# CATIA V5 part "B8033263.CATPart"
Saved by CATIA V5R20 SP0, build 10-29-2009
Part number: B8033263
Revision: 5
Definition: design
Nomenclature: B8033263
Source: made
Description: NOT SPECIFIED
Bounding box of the stored display mesh (mm): x -25 to 25, y -25 to 25, z 0 to 63
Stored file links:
  C:\Users\Utente\Desktop\3D files B803\B8033263.CATPart
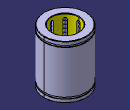
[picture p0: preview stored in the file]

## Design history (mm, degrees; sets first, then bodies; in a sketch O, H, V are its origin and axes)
Body1 "MANIFOLD_SOLID_BREP #38" (main body)
  Solid1: solid without history
Body2 "MANIFOLD_SOLID_BREP #76"
  Solid2: solid without history
Body3 "MANIFOLD_SOLID_BREP #114"
  Solid3: solid without history
Body4 "MANIFOLD_SOLID_BREP #152"
  Solid4: solid without history
Body5 "MANIFOLD_SOLID_BREP #190"
  Solid5: solid without history
Body6 "MANIFOLD_SOLID_BREP #228"
  Solid6: solid without history
Body7 "MANIFOLD_SOLID_BREP #266"
  Solid7: solid without history
Body8 "MANIFOLD_SOLID_BREP #304"
  Solid8: solid without history
Body9 "MANIFOLD_SOLID_BREP #2444"
  Solid9: solid without history
Body10 "MANIFOLD_SOLID_BREP #2482"
  Solid10: solid without history
Body11 "MANIFOLD_SOLID_BREP #2520"
  Solid11: solid without history
Body12 "MANIFOLD_SOLID_BREP #2558"
  Solid12: solid without history
Body13 "MANIFOLD_SOLID_BREP #2596"
  Solid13: solid without history
Body14 "MANIFOLD_SOLID_BREP #2634"
  Solid14: solid without history
Body15 "MANIFOLD_SOLID_BREP #2672"
  Solid15: solid without history
Body16 "MANIFOLD_SOLID_BREP #2710"
  Solid16: solid without history
Body17 "MANIFOLD_SOLID_BREP #2748"
  Solid17: solid without history
Body18 "MANIFOLD_SOLID_BREP #2786"
  Solid18: solid without history
Body19 "MANIFOLD_SOLID_BREP #2824"
  Solid19: solid without history
Body20 "MANIFOLD_SOLID_BREP #2862"
  Solid20: solid without history
Body21 "MANIFOLD_SOLID_BREP #2900"
  Solid21: solid without history
Body22 "MANIFOLD_SOLID_BREP #2938"
  Solid22: solid without history
Body23 "MANIFOLD_SOLID_BREP #2976"
  Solid23: solid without history
Body24 "MANIFOLD_SOLID_BREP #3014"
  Solid24: solid without history
Body25 "MANIFOLD_SOLID_BREP #3052"
  Solid25: solid without history
Body26 "MANIFOLD_SOLID_BREP #3090"
  Solid26: solid without history
Body27 "MANIFOLD_SOLID_BREP #3128"
  Solid27: solid without history
Body28 "MANIFOLD_SOLID_BREP #3166"
  Solid28: solid without history
Body29 "MANIFOLD_SOLID_BREP #3204"
  Solid29: solid without history
Body30 "MANIFOLD_SOLID_BREP #3242"
  Solid30: solid without history
Body31 "MANIFOLD_SOLID_BREP #3280"
  Solid31: solid without history
Body32 "MANIFOLD_SOLID_BREP #3318"
  Solid32: solid without history
Body33 "MANIFOLD_SOLID_BREP #3356"
  Solid33: solid without history
Body34 "MANIFOLD_SOLID_BREP #3394"
  Solid34: solid without history
Body35 "MANIFOLD_SOLID_BREP #3432"
  Solid35: solid without history
Body36 "MANIFOLD_SOLID_BREP #3470"
  Solid36: solid without history
Body37 "MANIFOLD_SOLID_BREP #3508"
  Solid37: solid without history
Body38 "MANIFOLD_SOLID_BREP #3546"
  Solid38: solid without history
Body39 "MANIFOLD_SOLID_BREP #3584"
  Solid39: solid without history
Body40 "MANIFOLD_SOLID_BREP #3622"
  Solid40: solid without history
Body41 "MANIFOLD_SOLID_BREP #3660"
  Solid41: solid without history
Body42 "MANIFOLD_SOLID_BREP #3698"
  Solid42: solid without history
Body43 "MANIFOLD_SOLID_BREP #3736"
  Solid43: solid without history
Body44 "MANIFOLD_SOLID_BREP #3774"
  Solid44: solid without history
Body45 "MANIFOLD_SOLID_BREP #3812"
  Solid45: solid without history
Body46 "MANIFOLD_SOLID_BREP #3850"
  Solid46: solid without history
Body47 "MANIFOLD_SOLID_BREP #3888"
  Solid47: solid without history
Body48 "MANIFOLD_SOLID_BREP #3926"
  Solid48: solid without history
Body49 "MANIFOLD_SOLID_BREP #3964"
  Solid49: solid without history
Body50 "MANIFOLD_SOLID_BREP #4002"
  Solid50: solid without history
Body51 "MANIFOLD_SOLID_BREP #4040"
  Solid51: solid without history
Body52 "MANIFOLD_SOLID_BREP #4078"
  Solid52: solid without history
Body53 "MANIFOLD_SOLID_BREP #4116"
  Solid53: solid without history
Body54 "MANIFOLD_SOLID_BREP #4154"
  Solid54: solid without history
Body55 "MANIFOLD_SOLID_BREP #4192"
  Solid55: solid without history
Body56 "MANIFOLD_SOLID_BREP #4230"
  Solid56: solid without history
Body57 "MANIFOLD_SOLID_BREP #4268"
  Solid57: solid without history
Body58 "MANIFOLD_SOLID_BREP #4306"
  Solid58: solid without history
Body59 "MANIFOLD_SOLID_BREP #4344"
  Solid59: solid without history
Body60 "MANIFOLD_SOLID_BREP #4382"
  Solid60: solid without history
Body61 "MANIFOLD_SOLID_BREP #4420"
  Solid61: solid without history
Body62 "MANIFOLD_SOLID_BREP #4458"
  Solid62: solid without history
Body63 "MANIFOLD_SOLID_BREP #4496"
  Solid63: solid without history
Body64 "MANIFOLD_SOLID_BREP #4534"
  Solid64: solid without history
Body65 "MANIFOLD_SOLID_BREP #4572"
  Solid65: solid without history
Body66 "MANIFOLD_SOLID_BREP #4610"
  Solid66: solid without history
Body67 "MANIFOLD_SOLID_BREP #4648"
  Solid67: solid without history
Body68 "MANIFOLD_SOLID_BREP #4686"
  Solid68: solid without history
Body69 "MANIFOLD_SOLID_BREP #4724"
  Solid69: solid without history
Body70 "MANIFOLD_SOLID_BREP #4762"
  Solid70: solid without history
Body71 "MANIFOLD_SOLID_BREP #4800"
  Solid71: solid without history
Body72 "MANIFOLD_SOLID_BREP #4838"
  Solid72: solid without history
Body73 "MANIFOLD_SOLID_BREP #4876"
  Solid73: solid without history
Body74 "MANIFOLD_SOLID_BREP #4914"
  Solid74: solid without history
Body75 "MANIFOLD_SOLID_BREP #4952"
  Solid75: solid without history
Body76 "MANIFOLD_SOLID_BREP #4990"
  Solid76: solid without history
Body77 "MANIFOLD_SOLID_BREP #5028"
  Solid77: solid without history
Body78 "MANIFOLD_SOLID_BREP #5066"
  Solid78: solid without history
Body79 "MANIFOLD_SOLID_BREP #5104"
  Solid79: solid without history
Body80 "MANIFOLD_SOLID_BREP #5142"
  Solid80: solid without history
Body81 "MANIFOLD_SOLID_BREP #5180"
  Solid81: solid without history
Body82 "MANIFOLD_SOLID_BREP #5218"
  Solid82: solid without history
Body83 "MANIFOLD_SOLID_BREP #5256"
  Solid83: solid without history
Body84 "MANIFOLD_SOLID_BREP #5294"
  Solid84: solid without history
Body85 "MANIFOLD_SOLID_BREP #5332"
  Solid85: solid without history
Body86 "MANIFOLD_SOLID_BREP #5370"
  Solid86: solid without history
Body87 "MANIFOLD_SOLID_BREP #5408"
  Solid87: solid without history
Body88 "MANIFOLD_SOLID_BREP #5446"
  Solid88: solid without history
Body89 "MANIFOLD_SOLID_BREP #5484"
  Solid89: solid without history
Body90 "MANIFOLD_SOLID_BREP #5522"
  Solid90: solid without history
Body91 "MANIFOLD_SOLID_BREP #5560"
  Solid91: solid without history
Body92 "MANIFOLD_SOLID_BREP #5598"
  Solid92: solid without history
Body93 "MANIFOLD_SOLID_BREP #5636"
  Solid93: solid without history
Body94 "MANIFOLD_SOLID_BREP #5674"
  Solid94: solid without history
Body95 "MANIFOLD_SOLID_BREP #5712"
  Solid95: solid without history
Body96 "MANIFOLD_SOLID_BREP #5750"
  Solid96: solid without history
Body97 "MANIFOLD_SOLID_BREP #5788"
  Solid97: solid without history
Body98 "MANIFOLD_SOLID_BREP #5826"
  Solid98: solid without history
Body99 "MANIFOLD_SOLID_BREP #5864"
  Solid99: solid without history
Body100 "MANIFOLD_SOLID_BREP #5902"
  Solid100: solid without history
Body101 "MANIFOLD_SOLID_BREP #5940"
  Solid101: solid without history
Body102 "MANIFOLD_SOLID_BREP #5978"
  Solid102: solid without history
Body103 "MANIFOLD_SOLID_BREP #6016"
  Solid103: solid without history
Body104 "MANIFOLD_SOLID_BREP #6054"
  Solid104: solid without history
Body105 "MANIFOLD_SOLID_BREP #6092"
  Solid105: solid without history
